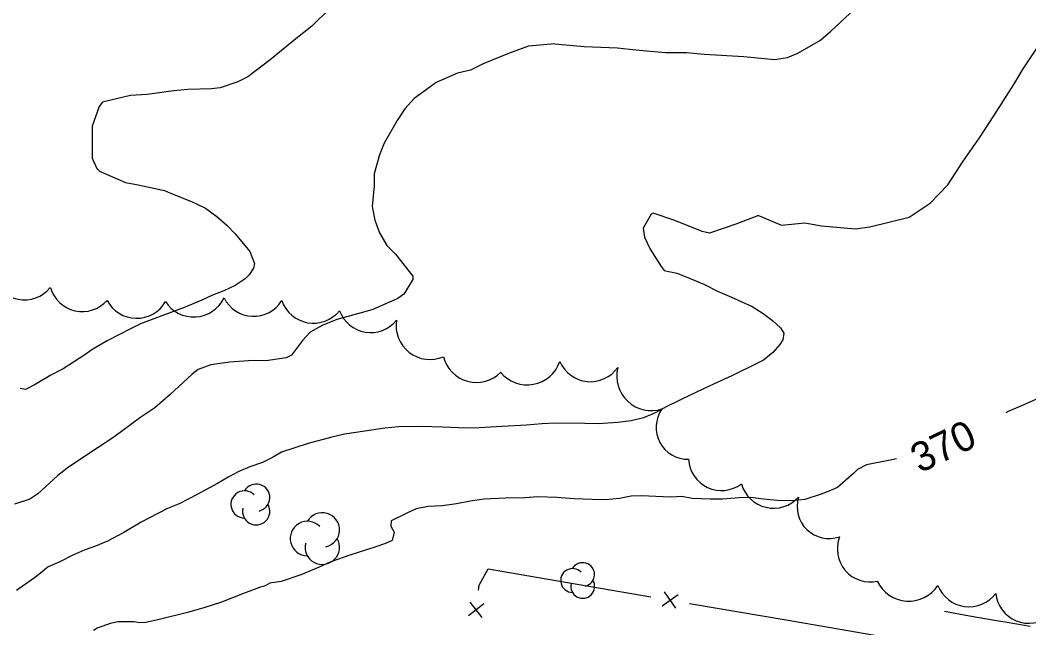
# Model space of a CAD drawing. Extents: x 287698 to 290158, y 5234163 to 5237182.
# Drawn here: x 288259.4 to 288362.3, y 5235855.1 to 5235917 of the extents above; entities that cross this region are included whole.
import ezdxf

# ---------------------------------------------------------------- set-up
doc = ezdxf.new("R2010")
doc.units = 0
for name, color, linetype in [('Niveau 1', 7, 'Continuous'), ('Niveau 2', 7, 'Continuous'), ('Niveau 37', 7, 'Continuous'), ('Niveau 4', 7, 'Continuous'), ('Niveau 44', 7, 'Continuous')]:
    doc.layers.add(name, color=color, linetype=linetype)

msp = doc.modelspace()

# ---------------------------------------------------------------- linework, layer by layer
at = {"layer": 'Niveau 1'}
for points in [[(288364.09, 5235878.83), (288361.83, 5235877.79)], [(288361.83, 5235877.79), (288360.21, 5235877.11), (288360, 5235876.98)], [(288348.82, 5235872.29), (288348.34, 5235872.19), (288345.78, 5235871.68), (288344.83, 5235871.21), (288344.46, 5235870.83), (288342.8, 5235869.37), (288342.27, 5235869.13), (288341.14, 5235868.7), (288339.47, 5235868.15), (288338.17, 5235868.02), (288336.7, 5235868.05), (288335.24, 5235868.17), (288333.96, 5235868.35), (288332.78, 5235868.3), (288331.09, 5235868.18), (288329.82, 5235868.19), (288327.98, 5235868.26), (288326.91, 5235868.45), (288325.82, 5235868.4), (288325.02, 5235868.41), (288322.82, 5235868.53), (288321.76, 5235868.49), (288320.55, 5235868.24), (288319.15, 5235868.12), (288317.78, 5235868.14), (288315.95, 5235868.22), (288314.18, 5235868.35), (288312.22, 5235868.41), (288310.9, 5235868.33), (288308.92, 5235868.28), (288306.77, 5235868.17), (288305.34, 5235867.99), (288303.92, 5235867.7), (288302.46, 5235867.5), (288301.05, 5235867.43), (288299.83, 5235867.18), (288298.86, 5235866.74), (288297.26, 5235865.96), (288297.23, 5235865.41), (288297.57, 5235864.81), (288297.38, 5235863.97), (288296.7, 5235863.64), (288295.62, 5235863.29), (288293.06, 5235862.47), (288291.1, 5235861.78), (288289.91, 5235861.25), (288288.04, 5235860.47), (288286.06, 5235859.77), (288284.9, 5235859.62), (288284.43, 5235859.35), (288283.84, 5235859.17), (288282.22, 5235858.56), (288279.95, 5235857.67), (288278.15, 5235857.08), (288276.5, 5235856.62), (288273.6, 5235855.89), (288272.23, 5235855.61), (288271.62, 5235855.56), (288271.03, 5235855.66), (288269.4, 5235855.68), (288268.65, 5235855.5), (288267.34, 5235855.06), (288266.9, 5235854.79)]]:
    msp.add_lwpolyline(points, dxfattribs=at)
at = {"layer": 'Niveau 2'}
for points in [[(288313.96, 5235914.62), (288316.96, 5235914.34), (288320.37, 5235914.22), (288322.24, 5235914.01), (288325.27, 5235913.73), (288327.39, 5235913.73), (288329.21, 5235913.58), (288333.24, 5235913.35), (288336.42, 5235913.04), (288337.71, 5235913.22), (288338.76, 5235913.69), (288341.07, 5235915.01), (288342.12, 5235915.93), (288344.53, 5235918.15), (288346.81, 5235920.26), (288349.94, 5235922.69), (288351.62, 5235923.9), (288353.47, 5235925.57), (288355.29, 5235927.39), (288356.97, 5235928.91), (288359.55, 5235931.41), (288360.76, 5235932.78), (288363.72, 5235935.6)], [(288289.19, 5235916.42), (288291.01, 5235918.23)], [(288289.19, 5235916.42), (288287.19, 5235914.85), (288284.93, 5235912.99), (288282.65, 5235911.27), (288281.62, 5235910.74), (288279.82, 5235910.15), (288278.93, 5235910.03), (288276.52, 5235909.98), (288275.09, 5235909.83), (288272.39, 5235909.47), (288270.68, 5235909.34), (288267.83, 5235908.67), (288267.49, 5235908.25), (288266.77, 5235906.22), (288266.77, 5235905.48), (288266.78, 5235902.96), (288267.25, 5235901.92), (288267.52, 5235901.65)], [(288313.96, 5235914.62), (288311.29, 5235914.4), (288309.23, 5235913.65), (288306.64, 5235912.58), (288305.35, 5235911.94), (288304.03, 5235911.62), (288301.86, 5235910.67), (288301.21, 5235910.22), (288299.61, 5235909.06), (288298.66, 5235907.99), (288297.88, 5235906.8), (288296.57, 5235904.48), (288296.09, 5235903.31), (288295.54, 5235901.37), (288295.53, 5235900.13), (288295.34, 5235898.04), (288295.59, 5235896.63), (288296.08, 5235895.36), (288296.82, 5235894.06), (288297.72, 5235893.18), (288299.49, 5235890.93), (288299.49, 5235890.58), (288298.55, 5235889.08), (288297.94, 5235888.66), (288295.41, 5235887.51), (288294.6, 5235887.28), (288291.72, 5235886.49), (288290.23, 5235885.91), (288289.02, 5235885.23), (288288.24, 5235884.35), (288287.1, 5235882.86), (288286.57, 5235882.58), (288284.53, 5235882.29), (288283.2, 5235882.32), (288280.78, 5235882.17), (288278.88, 5235881.89), (288277.59, 5235881.4), (288276.97, 5235880.94), (288274.72, 5235878.84), (288273.17, 5235877.5), (288271.74, 5235876.54), (288268.97, 5235874.52), (288267.37, 5235873.46), (288264.36, 5235871.45), (288263.25, 5235870.58), (288261.22, 5235868.72), (288260.4, 5235868.17), (288258.83, 5235867.67)], [(288334.74, 5235897.1), (288337.1, 5235896.14), (288339.46, 5235896.37), (288341.16, 5235896.05), (288344.65, 5235895.75), (288346.12, 5235895.97), (288350.11, 5235896.96), (288352.27, 5235898.39), (288354.05, 5235900.26), (288355.62, 5235902.66), (288357.3, 5235905.04), (288358.75, 5235907.27), (288360.8, 5235910.47), (288361.74, 5235912.07), (288363.87, 5235915.23)], [(288267.52, 5235901.65), (288270.18, 5235900.49), (288271.47, 5235900.24), (288274.15, 5235899.67), (288274.77, 5235899.4), (288276.89, 5235898.53), (288278.33, 5235897.85), (288279.49, 5235897.02), (288280.52, 5235896.13), (288281.35, 5235895.23), (288282.86, 5235893.46), (288283.33, 5235892.22), (288283.22, 5235891.73), (288282.78, 5235891.07), (288282.38, 5235890.67), (288281.36, 5235889.96), (288280.21, 5235889.43), (288279.03, 5235888.98), (288277.94, 5235888.47), (288276.1, 5235887.7), (288274.15, 5235886.99), (288271.71, 5235886.08), (288270.67, 5235885.57), (288268.29, 5235884.34), (288266.82, 5235883.48), (288265.9, 5235882.85), (288263.79, 5235881.46), (288262.55, 5235880.82), (288260.96, 5235879.88), (288259.96, 5235879.35), (288259.41, 5235879.48)], [(288334.74, 5235897.1), (288332.44, 5235896.23), (288329.75, 5235895.3), (288329, 5235895.49), (288326.22, 5235896.59), (288323.99, 5235897.34), (288323.8, 5235897.26), (288322.97, 5235895.81), (288323.1, 5235894.91), (288323.7, 5235893.69), (288324.82, 5235891.92), (288325.11, 5235891.52)], [(288325.11, 5235891.52), (288326.42, 5235891.23), (288327.37, 5235890.87), (288329.24, 5235890.06), (288330.57, 5235889.39), (288332, 5235888.79), (288334.11, 5235887.83), (288335.23, 5235887.12), (288336.16, 5235886.42), (288337, 5235885.67), (288337.34, 5235885.11), (288337.22, 5235884.44), (288336.91, 5235883.95), (288336.2, 5235883.13), (288335.26, 5235882.37), (288334.7, 5235882.1), (288332.02, 5235880.76), (288330.16, 5235879.9), (288327.85, 5235878.83), (288325.38, 5235877.64), (288324.19, 5235876.99), (288323.02, 5235876.49), (288321.77, 5235876.18), (288320.41, 5235876.01), (288318.38, 5235875.88), (288317.02, 5235875.91), (288314.05, 5235875.94), (288312.63, 5235875.87), (288311.07, 5235875.74), (288308.59, 5235875.6), (288305.67, 5235875.43), (288304.17, 5235875.44), (288302.54, 5235875.53), (288300.32, 5235875.6), (288298.05, 5235875.57), (288296.61, 5235875.41), (288294.6, 5235875.1), (288292.51, 5235874.82), (288291.21, 5235874.51), (288288.79, 5235873.87), (288286.08, 5235872.97), (288285.18, 5235872.42), (288284.13, 5235871.93), (288282.86, 5235871.49), (288281.74, 5235871.01), (288280.7, 5235870.47), (288279.56, 5235869.79), (288277.49, 5235868.64), (288275.64, 5235867.72), (288274.45, 5235867.22), (288273.45, 5235866.72), (288271.78, 5235865.83), (288269.99, 5235864.79), (288268.34, 5235863.91), (288267.11, 5235863.37), (288265.96, 5235862.96), (288264.71, 5235862.44), (288263.46, 5235861.79), (288262.29, 5235861.27), (288261.34, 5235860.49), (288260.87, 5235860.17), (288259.06, 5235858.86)]]:
    msp.add_lwpolyline(points, dxfattribs=at)
at = {"layer": 'Niveau 37'}
for p, q in [((288307.16, 5235861.06), (288323.75, 5235858.23)), ((288324.91, 5235857.31), (288326.55, 5235858.47)), ((288326.3, 5235857.07), (288325.15, 5235858.71)), ((288306.72, 5235857.51), (288305.15, 5235856.27)), ((288306.56, 5235856.11), (288305.32, 5235857.68)), ((288327.7, 5235857.55), (288337.56, 5235855.86)), ((288337.56, 5235855.86), (288347.41, 5235854.17))]:
    msp.add_line(p, q, dxfattribs=at)
msp.add_lwpolyline([(288306.17, 5235858.88), (288306.24, 5235859.42), (288307.16, 5235861.06)], dxfattribs=at)
at = {"layer": 'Niveau 4'}
msp.add_lwpolyline([(288353.71, 5235856.75), (288356.28, 5235856.29), (288358.84, 5235855.84), (288360.1, 5235855.62), (288362.46, 5235855.21)], dxfattribs=at)
at = {"layer": 'Niveau 44'}
for centre, radius, start, end in [((288277.13, 5235890.18), 3.42, 212.6471, 334.4458), ((288283.24, 5235890.2), 3.37, 206.3737, 328.3771), ((288311.15, 5235883.35), 3.51, 219.4963, 341.1802), ((288283.5, 5235868.33), 1.39, 282.2692, 149.7263), ((288282.31, 5235867.64), 1.39, 44.1154, 269.804), ((288283.5, 5235866.94), 1.39, 166.9369, 29.6212), ((288290.24, 5235865.04), 1.76, 282.2692, 149.7263), ((288288.73, 5235864.16), 1.76, 44.1154, 269.804), ((288290.24, 5235863.28), 1.76, 166.9369, 29.6212), ((288315.77, 5235859.88), 1.21, 44.1154, 269.804), ((288316.81, 5235860.49), 1.21, 282.2692, 149.7263), ((288316.81, 5235859.28), 1.21, 166.9369, 29.6212)]:
    msp.add_arc(centre, radius, start, end, dxfattribs=at)
for centre, major_axis, ratio, start_param, end_param in [((288259.84, 5235891.99), (-0.69, -3.41), 0.994237, 5.243055, 7.357987), ((288265.76, 5235890.72), (-0.74, -3.32), 0.997001, 5.216925, 7.34229), ((288271.3, 5235890.04), (-0.07, -3.41), 0.99995, 5.217523, 7.34842), ((288289.34, 5235889.56), (-0.77, -3.34), 0.998823, 5.2739, 7.399991), ((288295.18, 5235888.6), (-0.54, -3.39), 0.985608, 5.224376, 7.331188), ((288301.27, 5235885.93), (-2.18, -2.76), 0.991677, 5.232338, 7.346793), ((288305.97, 5235883.54), (-0.91, -3.34), 0.999978, 5.222809, 7.345271), ((288317.6, 5235883.59), (-0.43, -3.4), 0.996043, 5.249554, 7.36487), ((288323.82, 5235880.75), (-2.56, -2.45), 0.998742, 5.276688, 7.400947), ((288327.66, 5235875.58), (-2.65, -2.13), 0.968706, 5.021149, 7.177185), ((288330.99, 5235872.46), (-1.33, -3.13), 0.994434, 5.173473, 7.322015), ((288336.29, 5235870.68), (-1.8, -2.91), 0.999961, 5.546554, 7.67322), ((288342.04, 5235867.52), (-2.24, -2.55), 0.974911, 5.160809, 7.315659), ((288346.16, 5235863.12), (-1.81, -2.87), 0.991121, 4.907412, 7.06406), ((288350.08, 5235861.32), (-0.25, -3.54), 0.999578, 5.219191, 7.34764), ((288356.23, 5235860.61), (-0.71, -3.33), 0.999251, 5.290652, 7.420738), ((288362.33, 5235858.91), (-1.43, -3.08), 0.999978, 5.251381, 7.405105)]:
    msp.add_ellipse(centre, major_axis=major_axis, ratio=ratio, start_param=start_param, end_param=end_param, dxfattribs=at)

# ---------------------------------------------------------------- texts
at = {"layer": 'Niveau 1'}
msp.add_text('370', height=3, rotation=25.568, dxfattribs=at).set_placement((288351.2, 5235870.79))

doc.saveas('drawing.dxf')
